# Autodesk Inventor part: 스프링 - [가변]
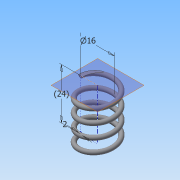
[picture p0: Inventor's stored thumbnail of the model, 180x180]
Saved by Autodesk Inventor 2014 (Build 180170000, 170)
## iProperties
Created: 2015-04
Part Number: 스프링 - [가변]
Material: Generic
Document SubType Name: Modeling
Designer: Administrator
Density: 1 g/cm^3
Appearance: Default
Mass: 0.608323 g
Surface Area: 12.5242 cm^2
Volume: 0.608323 cm^3
Author: Administrator
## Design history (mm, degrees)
sketch "스케치1"
  geometry: L1 (0, 0)-(-8, 0); L2 (-8, 0)-(-8, 11.5); L3 (-8, 11.5)-(0, 11.5); L4 (0, 11.5)-(0, 0); C1 r 1 at (-8, 0)
  constraints: 8 end point, 2 parallel, 1 centre point, 1 coincident, 1 horizontal, 1 perpendicular
  dimensions: "d0" = 16 diameter of L2 L4; "d1" = 11.50049 distance between parallel lines of L1 L3 (derived); "d2" = 2 diameter of C1
feature "코일1" pitch "d3" = 10; turns "d5" = 4; dims "d4" = 11.50049 (= d1), "d6" = 0, angle "d7" = 90 deg, angle "d8" = 90 deg, "d9" = 0, "d10" = 0
sketch "스케치2"
  geometry: L1 (9, 0)-(7, 0) reference; 1 further point
  constraints: 1 horizontal alignment
extrude "돌출1" cut sketch "스케치2" stored distance "d11" = 10; taper "d12" = 0 deg
node "작업 평면1"
sketch "스케치3"
  geometry: L1 (-9, 0)-(-7, 0) reference; 1 further point
  constraints: 1 horizontal alignment
extrude "돌출2" cut sketch "스케치3" stored distance "d13" = 10; taper "d14" = 0 deg
node "솔리드1"
node "절단 모서리 투영1"
node "절단 모서리 투영2"
